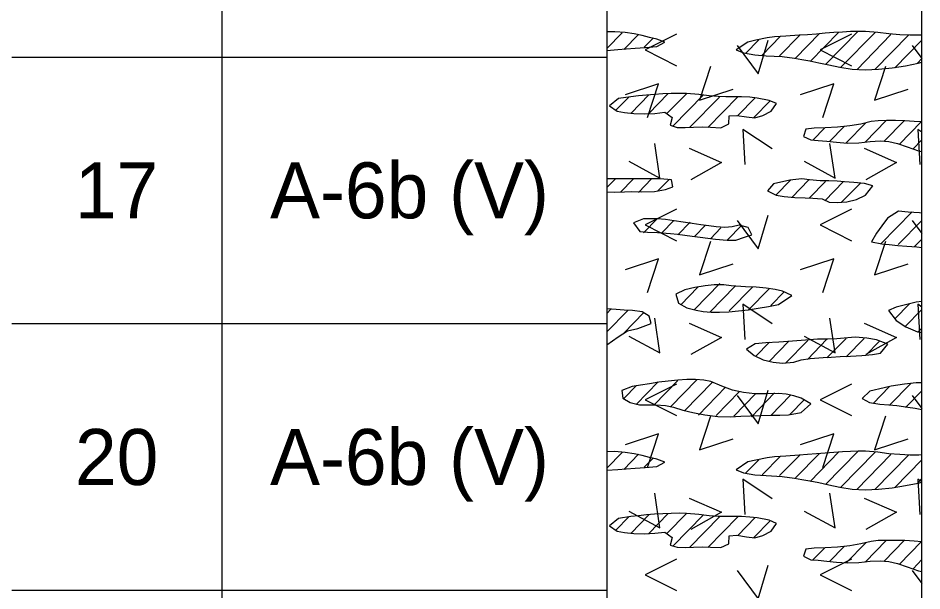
# Model space of a CAD drawing. Extents: x 0 to 0.833, y -0.323 to 0.608.
# Drawn here: x 0.7258 to 0.8333, y 0.4127 to 0.4809 of the extents above; entities that cross this region are included whole.
import ezdxf

# ---------------------------------------------------------------- set-up
doc = ezdxf.new("R2010")
doc.units = 0

msp = doc.modelspace()

# ---------------------------------------------------------------- linework, layer by layer
for points in [[(0, -0.32328), (0.83333, -0.32328), (0.83333, 0.60833), (0, 0.60833)], [(0.79583, 0.47704), (0.79715, 0.47715), (0.79814, 0.47722), (0.79922, 0.4773), (0.80039, 0.47738), (0.80179, 0.47751), (0.80275, 0.47802), (0.80179, 0.47836), (0.80091, 0.47858), (0.80003, 0.4788), (0.79909, 0.479), (0.79803, 0.47917), (0.79677, 0.47927), (0.79583, 0.47925)], [(0.82816, 0.47479), (0.82978, 0.47496), (0.83137, 0.47521), (0.8329, 0.47552), (0.83333, 0.47563), (0.83333, 0.47887), (0.83295, 0.47884), (0.83188, 0.47886), (0.83071, 0.47891), (0.82938, 0.47901), (0.82807, 0.47918), (0.82662, 0.4793), (0.82576, 0.4793), (0.82484, 0.47928), (0.82387, 0.47923), (0.82286, 0.47916), (0.82182, 0.47908), (0.82077, 0.47899), (0.81973, 0.47891), (0.81872, 0.47884), (0.81715, 0.47874), (0.81579, 0.47865), (0.81491, 0.47852), (0.81357, 0.47824), (0.8126, 0.47803), (0.81121, 0.47711), (0.8121, 0.47675), (0.81345, 0.4765), (0.81479, 0.47641), (0.81668, 0.47631), (0.81818, 0.47611), (0.81905, 0.47596), (0.82, 0.47578), (0.82107, 0.47557), (0.82225, 0.47532), (0.82357, 0.47503), (0.82501, 0.4748), (0.82656, 0.47473)], [(0.79708, 0.46981), (0.79794, 0.46963), (0.79904, 0.46952), (0.80028, 0.46949), (0.80156, 0.46954), (0.80274, 0.46969), (0.80361, 0.46903), (0.80338, 0.46814), (0.80422, 0.46787), (0.80517, 0.46785), (0.80613, 0.4679), (0.8072, 0.46793), (0.80818, 0.4679), (0.80939, 0.46783), (0.81037, 0.46829), (0.81038, 0.46924), (0.8113, 0.4693), (0.81244, 0.46912), (0.81346, 0.46901), (0.81438, 0.46927), (0.81539, 0.46981), (0.81601, 0.47072), (0.81517, 0.47109), (0.81374, 0.47137), (0.81285, 0.47146), (0.81187, 0.47152), (0.81, 0.47152), (0.8091, 0.47154), (0.808, 0.47162), (0.80678, 0.47177), (0.8053, 0.4719), (0.80443, 0.47192), (0.80349, 0.4719), (0.80251, 0.47186), (0.80152, 0.4718), (0.80054, 0.47172), (0.79959, 0.47163), (0.7987, 0.47153), (0.79722, 0.47131), (0.79614, 0.47043)], [(0.83241, 0.46859), (0.83129, 0.46866), (0.83017, 0.46869), (0.8291, 0.46869), (0.82811, 0.46866), (0.82728, 0.46857), (0.82608, 0.46827), (0.82476, 0.46804), (0.8233, 0.4679), (0.82183, 0.46782), (0.82051, 0.46776), (0.81951, 0.46766), (0.81922, 0.4668), (0.82013, 0.46638), (0.82097, 0.46633), (0.822, 0.46623), (0.82318, 0.4661), (0.82448, 0.46601), (0.82584, 0.46604), (0.82719, 0.4662), (0.82836, 0.46627), (0.8294, 0.46619), (0.83043, 0.46595), (0.83156, 0.46556), (0.83291, 0.46507), (0.83333, 0.465), (0.83333, 0.46852)], [(0.79583, 0.46018), (0.79676, 0.46017), (0.79792, 0.46019), (0.79882, 0.46023), (0.79992, 0.46018), (0.80151, 0.46023), (0.80282, 0.46048), (0.80367, 0.4608), (0.80354, 0.46164), (0.80216, 0.46173), (0.79583, 0.46173)], [(0.81822, 0.45953), (0.81944, 0.45947), (0.82033, 0.45943), (0.82145, 0.45937), (0.82229, 0.45895), (0.82324, 0.45891), (0.82438, 0.45901), (0.82555, 0.4593), (0.82662, 0.45981), (0.82749, 0.4609), (0.82651, 0.46121), (0.82524, 0.46131), (0.82413, 0.46137), (0.82324, 0.46148), (0.82226, 0.4615), (0.82121, 0.46152), (0.81995, 0.46161), (0.81902, 0.46173), (0.81761, 0.46159), (0.81566, 0.46114), (0.81496, 0.46031), (0.81598, 0.45982), (0.81695, 0.45964)], [(0.83305, 0.45768), (0.83171, 0.45779), (0.83054, 0.45789), (0.82925, 0.45707), (0.82857, 0.45616), (0.82792, 0.45527), (0.82735, 0.45424), (0.82858, 0.45402), (0.82945, 0.45392), (0.83045, 0.45382), (0.83155, 0.45373), (0.83272, 0.45363), (0.83333, 0.45358), (0.83333, 0.45767)], [(0.80066, 0.45538), (0.80188, 0.45537), (0.80339, 0.45524), (0.80423, 0.45515), (0.8051, 0.45504), (0.806, 0.45492), (0.80692, 0.4548), (0.80784, 0.45468), (0.80875, 0.45457), (0.81014, 0.45443), (0.81119, 0.45444), (0.81222, 0.45478), (0.81308, 0.45507), (0.81267, 0.45597), (0.8116, 0.45622), (0.81075, 0.45602), (0.80989, 0.45594), (0.80885, 0.45602), (0.80799, 0.45613), (0.80703, 0.45627), (0.806, 0.45644), (0.80492, 0.4566), (0.80384, 0.45676), (0.8028, 0.45689), (0.80182, 0.45698), (0.8002, 0.45699), (0.79901, 0.45652), (0.79974, 0.45548)], [(0.81233, 0.44887), (0.81063, 0.44899), (0.80977, 0.44912), (0.8086, 0.44913), (0.80755, 0.44899), (0.80632, 0.44879), (0.80513, 0.44854), (0.80403, 0.44802), (0.80436, 0.44696), (0.80536, 0.44639), (0.80647, 0.4461), (0.8073, 0.44595), (0.80824, 0.44587), (0.80926, 0.44586), (0.81035, 0.44591), (0.81149, 0.44601), (0.81267, 0.44616), (0.81386, 0.44635), (0.81506, 0.44656), (0.81625, 0.44679), (0.81783, 0.44787), (0.81673, 0.44837), (0.81585, 0.44857), (0.8148, 0.44873), (0.81361, 0.44883)], [(0.83265, 0.44706), (0.83136, 0.44675), (0.83028, 0.44647), (0.82934, 0.44608), (0.83026, 0.44488), (0.83142, 0.44412), (0.83279, 0.44354), (0.83333, 0.44344), (0.83333, 0.44715)], [(0.79583, 0.44196), (0.79719, 0.44295), (0.79831, 0.44365), (0.79951, 0.44392), (0.80111, 0.44453), (0.80086, 0.44541), (0.80002, 0.44589), (0.79889, 0.44608), (0.79791, 0.44611), (0.79694, 0.44617), (0.79583, 0.44625)], [(0.82537, 0.4429), (0.82408, 0.44276), (0.82319, 0.4427), (0.82214, 0.44267), (0.82091, 0.44264), (0.81947, 0.44254), (0.81792, 0.44242), (0.81632, 0.4423), (0.81475, 0.44221), (0.81348, 0.44211), (0.81247, 0.44147), (0.81337, 0.44071), (0.81444, 0.44021), (0.81561, 0.43992), (0.81675, 0.43981), (0.81807, 0.43993), (0.81896, 0.4402), (0.82003, 0.44035), (0.82157, 0.44047), (0.82253, 0.44052), (0.82362, 0.44058), (0.82483, 0.44064), (0.82618, 0.44071), (0.82745, 0.44082), (0.82842, 0.44099), (0.82927, 0.44205), (0.82791, 0.44257), (0.82679, 0.44277)], [(0.79885, 0.437), (0.79763, 0.43654), (0.79773, 0.43564), (0.79859, 0.43512), (0.7997, 0.43482), (0.80074, 0.43483), (0.80165, 0.43484), (0.80281, 0.43476), (0.80377, 0.43455), (0.80486, 0.4342), (0.80606, 0.43391), (0.80751, 0.43363), (0.80905, 0.43345), (0.81052, 0.43342), (0.81177, 0.43347), (0.81289, 0.43351), (0.81408, 0.43355), (0.81553, 0.43359), (0.81642, 0.43362), (0.81745, 0.43365), (0.81897, 0.43392), (0.82011, 0.43496), (0.81896, 0.43563), (0.8181, 0.43589), (0.81717, 0.43609), (0.81626, 0.43619), (0.81479, 0.43614), (0.81343, 0.43614), (0.8121, 0.43629), (0.8108, 0.43659), (0.80953, 0.43705), (0.8082, 0.4376), (0.80736, 0.43776), (0.8064, 0.43784), (0.80536, 0.43784), (0.80427, 0.43778), (0.80314, 0.43767), (0.80201, 0.43752), (0.8009, 0.43735), (0.79984, 0.43717)], [(0.83263, 0.43744), (0.83126, 0.4373), (0.82969, 0.43704), (0.82883, 0.43687), (0.82712, 0.43646), (0.82623, 0.43559), (0.82708, 0.4351), (0.82831, 0.43491), (0.82941, 0.43484), (0.83033, 0.43475), (0.83165, 0.43457), (0.83253, 0.43443), (0.83333, 0.43429), (0.83333, 0.43744)], [(0.79583, 0.42704), (0.79715, 0.42715), (0.79814, 0.42722), (0.79922, 0.4273), (0.80039, 0.42738), (0.80179, 0.42751), (0.80275, 0.42802), (0.80179, 0.42836), (0.80091, 0.42858), (0.80003, 0.4288), (0.79909, 0.429), (0.79803, 0.42917), (0.79677, 0.42927), (0.79583, 0.42925)], [(0.82816, 0.42479), (0.82978, 0.42496), (0.83137, 0.42521), (0.8329, 0.42552), (0.83333, 0.42563), (0.83333, 0.42887), (0.83295, 0.42884), (0.83188, 0.42886), (0.83071, 0.42891), (0.82938, 0.42901), (0.82807, 0.42918), (0.82662, 0.4293), (0.82576, 0.4293), (0.82484, 0.42928), (0.82387, 0.42923), (0.82286, 0.42916), (0.82182, 0.42908), (0.82077, 0.42899), (0.81973, 0.42891), (0.81872, 0.42884), (0.81715, 0.42874), (0.81579, 0.42865), (0.81491, 0.42852), (0.81357, 0.42824), (0.8126, 0.42803), (0.81121, 0.42711), (0.8121, 0.42675), (0.81345, 0.4265), (0.81479, 0.42641), (0.81668, 0.42631), (0.81818, 0.42611), (0.81905, 0.42596), (0.82, 0.42578), (0.82107, 0.42557), (0.82225, 0.42532), (0.82357, 0.42503), (0.82501, 0.4248), (0.82656, 0.42473)], [(0.79708, 0.41981), (0.79794, 0.41963), (0.79904, 0.41952), (0.80028, 0.41949), (0.80156, 0.41954), (0.80274, 0.41969), (0.80361, 0.41903), (0.80338, 0.41814), (0.80422, 0.41787), (0.80517, 0.41785), (0.80613, 0.4179), (0.8072, 0.41793), (0.80818, 0.4179), (0.80939, 0.41783), (0.81037, 0.4183), (0.81038, 0.41924), (0.8113, 0.4193), (0.81244, 0.41912), (0.81346, 0.41901), (0.81438, 0.41927), (0.81539, 0.41981), (0.81601, 0.42072), (0.81517, 0.42109), (0.81374, 0.42137), (0.81285, 0.42146), (0.81187, 0.42152), (0.81, 0.42152), (0.8091, 0.42154), (0.808, 0.42162), (0.80678, 0.42177), (0.8053, 0.4219), (0.80443, 0.42192), (0.80349, 0.4219), (0.80251, 0.42186), (0.80152, 0.4218), (0.80054, 0.42172), (0.79959, 0.42163), (0.7987, 0.42153), (0.79722, 0.42131), (0.79614, 0.42043)], [(0.83241, 0.41859), (0.83129, 0.41866), (0.83017, 0.41869), (0.8291, 0.41869), (0.82811, 0.41866), (0.82728, 0.41857), (0.82608, 0.41827), (0.82476, 0.41804), (0.8233, 0.4179), (0.82183, 0.41782), (0.82051, 0.41776), (0.81951, 0.41766), (0.81922, 0.4168), (0.82013, 0.41638), (0.82097, 0.41633), (0.822, 0.41623), (0.82318, 0.4161), (0.82448, 0.41601), (0.82584, 0.41604), (0.82719, 0.4162), (0.82836, 0.41627), (0.8294, 0.41619), (0.83043, 0.41595), (0.83156, 0.41556), (0.83291, 0.41507), (0.83333, 0.415), (0.83333, 0.41852)]]:
    msp.add_lwpolyline(points, close=True)
for points in [[(0.75, 0.55417), (0.75, -0.28575)], [(0.75, 0.55417), (0.75, -0.28575)], [(0.79583, 0.55417), (0.79583, -0.28575)], [(0.83333, -0.28575), (0.83333, 0.50165)], [(0.79765, 0.47915), (0.79583, 0.47728)], [(0.7996, 0.47894), (0.79786, 0.47715)], [(0.80412, 0.47896), (0.80038, 0.47709), (0.80412, 0.47521)], [(0.8143, 0.47648), (0.8165, 0.47873)], [(0.8164, 0.47641), (0.81879, 0.47886)], [(0.81829, 0.47613), (0.82114, 0.47905)], [(0.82004, 0.47571), (0.82346, 0.47922)], [(0.82496, 0.47896), (0.82121, 0.47709), (0.82496, 0.47521)], [(0.82569, 0.47929), (0.82184, 0.47535)], [(0.82775, 0.47919), (0.8237, 0.47504)], [(0.82964, 0.47892), (0.82557, 0.47474)], [(0.83173, 0.47885), (0.82774, 0.47476)], [(0.8013, 0.47846), (0.80027, 0.47741)], [(0.81134, 0.47762), (0.81384, 0.47425), (0.81503, 0.47825)], [(0.81392, 0.4783), (0.81235, 0.47669)], [(0.83333, 0.47827), (0.83012, 0.47498)], [(0.83217, 0.47762), (0.83333, 0.47606)], [(0.725, 0.47625), (0.75, 0.47625)], [(0.75, 0.47625), (0.79583, 0.47625)], [(0.83281, 0.47552), (0.83333, 0.47606)], [(0.80818, 0.47513), (0.80687, 0.47113), (0.81087, 0.47244)], [(0.82901, 0.47513), (0.8277, 0.47113), (0.8317, 0.47244)], [(0.80069, 0.46905), (0.802, 0.47305), (0.798, 0.47174)], [(0.82152, 0.46905), (0.82284, 0.47305), (0.81884, 0.47174)], [(0.79844, 0.47149), (0.79691, 0.46992)], [(0.79871, 0.46955), (0.80085, 0.47174)], [(0.80083, 0.46951), (0.80311, 0.47185)], [(0.80534, 0.47192), (0.80299, 0.46951)], [(0.80367, 0.468), (0.80732, 0.47174)], [(0.80571, 0.46788), (0.80924, 0.47149)], [(0.81142, 0.47151), (0.80785, 0.46786)], [(0.81141, 0.46929), (0.81348, 0.47141)], [(0.81528, 0.47104), (0.81331, 0.46903)], [(0.82233, 0.46619), (0.82408, 0.46798)], [(0.82433, 0.46602), (0.82666, 0.46841)], [(0.82909, 0.46869), (0.82656, 0.4661)], [(0.82885, 0.46623), (0.83122, 0.46866)], [(0.83325, 0.46852), (0.83065, 0.46586)], [(0.81551, 0.46533), (0.81201, 0.46764), (0.81226, 0.46345)], [(0.82035, 0.46637), (0.82176, 0.46782)], [(0.83333, 0.46732), (0.83284, 0.46764), (0.83309, 0.46345)], [(0.79847, 0.46384), (0.80215, 0.46184), (0.80153, 0.46597)], [(0.8193, 0.46384), (0.82299, 0.46184), (0.82236, 0.46597)], [(0.83333, 0.4664), (0.83227, 0.46531)], [(0.80562, 0.46539), (0.80946, 0.46371), (0.80581, 0.46164)], [(0.82645, 0.46539), (0.83029, 0.46371), (0.82664, 0.46164)], [(0.79583, 0.4607), (0.79681, 0.4617)], [(0.79898, 0.46171), (0.79747, 0.46017)], [(0.80116, 0.46173), (0.79959, 0.46013)], [(0.80328, 0.46169), (0.80188, 0.46026)], [(0.8177, 0.46159), (0.81596, 0.45981)], [(0.81988, 0.46161), (0.81785, 0.45953)], [(0.82185, 0.46142), (0.81997, 0.45949)], [(0.824, 0.46141), (0.82178, 0.45913)], [(0.82601, 0.46125), (0.82378, 0.45897)], [(0.80412, 0.45813), (0.80038, 0.45626), (0.80412, 0.45438)], [(0.81134, 0.45679), (0.81384, 0.45341), (0.81503, 0.45741)], [(0.82496, 0.45813), (0.82121, 0.45626), (0.82496, 0.45438)], [(0.83217, 0.45781), (0.82844, 0.45399)], [(0.80188, 0.45703), (0.8002, 0.45531)], [(0.8038, 0.45679), (0.80237, 0.45532)], [(0.80575, 0.45657), (0.80429, 0.45508)], [(0.80758, 0.45624), (0.80627, 0.45489)], [(0.81188, 0.45621), (0.81016, 0.45446)], [(0.83333, 0.45679), (0.83052, 0.45391)], [(0.83217, 0.45679), (0.83333, 0.45523)], [(0.80941, 0.4559), (0.80816, 0.45462)], [(0.80818, 0.4543), (0.80687, 0.4503), (0.81087, 0.45161)], [(0.82901, 0.4543), (0.8277, 0.4503), (0.8317, 0.45161)], [(0.83333, 0.45457), (0.83245, 0.45367)], [(0.80069, 0.44822), (0.802, 0.45222), (0.798, 0.45091)], [(0.82152, 0.44822), (0.82284, 0.45222), (0.81884, 0.45091)], [(0.80465, 0.44675), (0.80667, 0.44883)], [(0.80626, 0.44619), (0.80928, 0.44928)], [(0.80809, 0.44585), (0.81111, 0.44895)], [(0.81041, 0.44602), (0.81318, 0.44885)], [(0.81264, 0.44609), (0.81518, 0.44869)], [(0.81536, 0.44667), (0.81699, 0.44833)], [(0.81551, 0.44449), (0.81201, 0.44681), (0.81226, 0.44262)], [(0.8301, 0.44509), (0.83184, 0.44687)], [(0.83333, 0.44648), (0.83284, 0.44681), (0.83309, 0.44262)], [(0.7963, 0.44621), (0.79583, 0.44572)], [(0.79834, 0.44608), (0.79583, 0.44351)], [(0.79786, 0.44338), (0.80023, 0.44581)], [(0.83131, 0.44412), (0.83333, 0.44619)], [(0.725, 0.4445), (0.75, 0.4445)], [(0.75, 0.4445), (0.79583, 0.4445)], [(0.79847, 0.44301), (0.80215, 0.44101), (0.80153, 0.44514)], [(0.80562, 0.44456), (0.80946, 0.44287), (0.80581, 0.44081)], [(0.8193, 0.44301), (0.82299, 0.44101), (0.82236, 0.44514)], [(0.82645, 0.44456), (0.83029, 0.44287), (0.82664, 0.44081)], [(0.83285, 0.44349), (0.83333, 0.44398)], [(0.81519, 0.44228), (0.81354, 0.44058)], [(0.81514, 0.44001), (0.81748, 0.44241)], [(0.81709, 0.4398), (0.81974, 0.44251)], [(0.8197, 0.44025), (0.82203, 0.44265)], [(0.82202, 0.44042), (0.8243, 0.44275)], [(0.82431, 0.44055), (0.82644, 0.44274)], [(0.82663, 0.44071), (0.82834, 0.44247)], [(0.80653, 0.43783), (0.8034, 0.43461)], [(0.79938, 0.43713), (0.79786, 0.43558)], [(0.79933, 0.43487), (0.80195, 0.43756)], [(0.80412, 0.4373), (0.80038, 0.43542), (0.80412, 0.43355)], [(0.80142, 0.4348), (0.8043, 0.43775)], [(0.80506, 0.4341), (0.8084, 0.43752)], [(0.80997, 0.43693), (0.80675, 0.43362)], [(0.82496, 0.4373), (0.82121, 0.43542), (0.82496, 0.43355)], [(0.82751, 0.43498), (0.82945, 0.43696)], [(0.83203, 0.43739), (0.82949, 0.43479)], [(0.81164, 0.43642), (0.80884, 0.43356)], [(0.81353, 0.43614), (0.81094, 0.43349)], [(0.81134, 0.43596), (0.81384, 0.43258), (0.81503, 0.43658)], [(0.81303, 0.43342), (0.81579, 0.43625)], [(0.81534, 0.43358), (0.81768, 0.43597)], [(0.83138, 0.43452), (0.83333, 0.43652)], [(0.83217, 0.43596), (0.83333, 0.43439)], [(0.8176, 0.43368), (0.81934, 0.43547)], [(0.83333, 0.4343), (0.83333, 0.4343)], [(0.80818, 0.43347), (0.80687, 0.42947), (0.81087, 0.43078)], [(0.82901, 0.43347), (0.8277, 0.42947), (0.8317, 0.43078)], [(0.80069, 0.42739), (0.802, 0.43139), (0.798, 0.43007)], [(0.82152, 0.42739), (0.82284, 0.43139), (0.81884, 0.43007)], [(0.82004, 0.42571), (0.82346, 0.42922)], [(0.82569, 0.42929), (0.82184, 0.42535)], [(0.79765, 0.42915), (0.79583, 0.42728)], [(0.7996, 0.42894), (0.79786, 0.42715)], [(0.8013, 0.42846), (0.80027, 0.42741)], [(0.81392, 0.4283), (0.81235, 0.42669)], [(0.8143, 0.42648), (0.8165, 0.42873)], [(0.8164, 0.42641), (0.81879, 0.42886)], [(0.81829, 0.42613), (0.82114, 0.42905)], [(0.82775, 0.42919), (0.8237, 0.42504)], [(0.82964, 0.42892), (0.82557, 0.42474)], [(0.83173, 0.42885), (0.82774, 0.42476)], [(0.83333, 0.42827), (0.83012, 0.42498)], [(0.83281, 0.42552), (0.83333, 0.42606)], [(0.81551, 0.42366), (0.81201, 0.42597), (0.81226, 0.42178)], [(0.83333, 0.42565), (0.83284, 0.42597), (0.83309, 0.42178)], [(0.79847, 0.42218), (0.80215, 0.42018), (0.80153, 0.4243)], [(0.8193, 0.42218), (0.82299, 0.42018), (0.82236, 0.4243)], [(0.80562, 0.42372), (0.80946, 0.42204), (0.80581, 0.41998)], [(0.82645, 0.42372), (0.83029, 0.42204), (0.82664, 0.41998)], [(0.79871, 0.41955), (0.80085, 0.42174)], [(0.80083, 0.41951), (0.80311, 0.42185)], [(0.80534, 0.42192), (0.80299, 0.41951)], [(0.80367, 0.418), (0.80732, 0.42174)], [(0.79844, 0.42149), (0.79691, 0.41992)], [(0.80571, 0.41788), (0.80924, 0.42149)], [(0.81142, 0.42151), (0.80785, 0.41786)], [(0.81141, 0.41929), (0.81348, 0.42141)], [(0.81528, 0.42104), (0.81331, 0.41903)], [(0.82909, 0.41869), (0.82656, 0.4161)], [(0.82885, 0.41623), (0.83122, 0.41866)], [(0.83325, 0.41852), (0.83065, 0.41586)], [(0.82035, 0.41637), (0.82176, 0.41782)], [(0.82233, 0.41619), (0.82408, 0.41798)], [(0.82433, 0.41602), (0.82666, 0.41841)], [(0.80412, 0.41646), (0.80038, 0.41459), (0.80412, 0.41271)], [(0.82496, 0.41646), (0.82121, 0.41459), (0.82496, 0.41271)], [(0.83333, 0.4164), (0.83227, 0.41531)], [(0.81134, 0.41512), (0.81384, 0.41175), (0.81503, 0.41575)], [(0.83217, 0.41512), (0.83333, 0.41356)], [(0.725, 0.41275), (0.75, 0.41275)], [(0.75, 0.41275), (0.79583, 0.41275)]]:
    msp.add_lwpolyline(points)

# ---------------------------------------------------------------- texts
for s, p in [('17', (0.73253, 0.45704)), ('A-6b (V)', (0.75575, 0.45704)), ('20', (0.73254, 0.42529)), ('A-6b (V)', (0.75575, 0.42529))]:
    msp.add_text(s, height=0.006667).set_placement(p)

doc.saveas('drawing.dxf')
